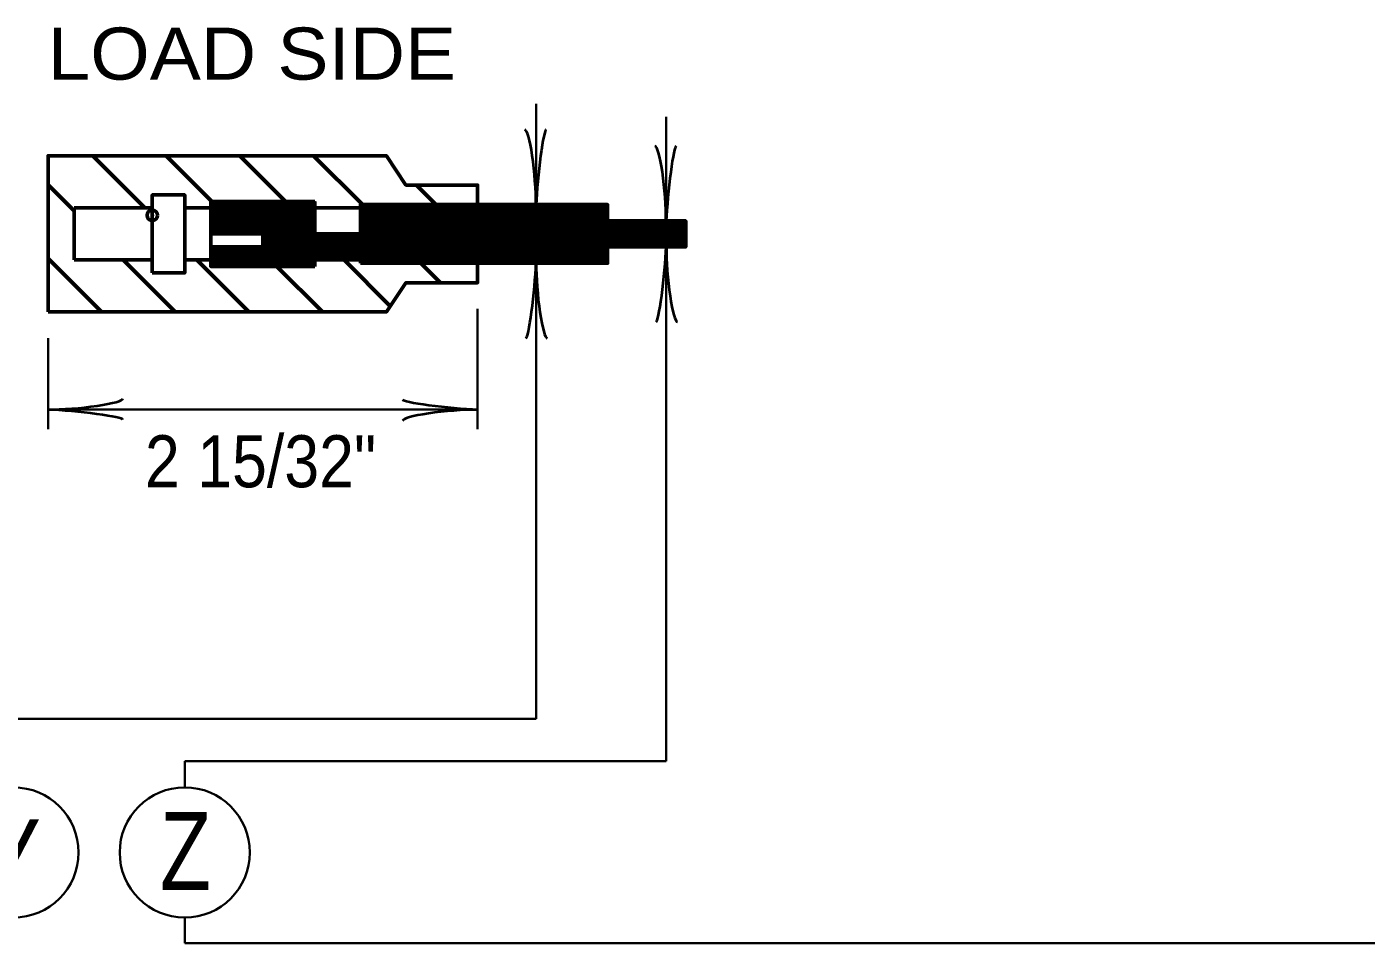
# Model space of a CAD drawing. Extents: x -1 to 679, y 0 to 440.
# Drawn here: x 531 to 582.5, y 359.2 to 394.4 of the extents above; entities that cross this region are included whole.
import ezdxf

# ---------------------------------------------------------------- set-up
doc = ezdxf.new("R2010")
doc.units = 0
doc.header["$LTSCALE"] = 0.8
doc.header["$PDMODE"] = 32
doc.header["$PDSIZE"] = 0.4
doc.layers.add('1', color=7, linetype='Continuous', lineweight=53)

msp = doc.modelspace()

# ---------------------------------------------------------------- linework, layer by layer
at = {"layer": '1', "lineweight": 35}
for p, q in [((550.6135, 387.6022), (550.6135, 391.4772)), ((555.6135, 386.9772), (555.6135, 390.9772)), ((555.6135, 385.9772), (555.6135, 366.2272)), ((550.6135, 385.3522), (550.6135, 367.8522)), ((548.3635, 383.6022), (548.3635, 378.9772)), ((531.8635, 382.4772), (531.8635, 378.9772)), ((531.8635, 379.7272), (548.3635, 379.7272)), ((550.6135, 367.8522), (530.5331, 367.8522)), ((555.6135, 366.2272), (537.1135, 366.2272)), ((537.1135, 366.2272), (537.1135, 365.2133)), ((537.1135, 360.2133), (537.1135, 359.2272)), ((537.1135, 359.2272), (624.4022, 359.2272))]:
    msp.add_line(p, q, dxfattribs=at)
at = {"layer": '1'}
for p, q in [((535.5778, 387.4772), (533.5777, 389.4772)), ((538.1561, 387.7272), (536.4061, 389.4772)), ((540.9847, 387.7272), (539.2346, 389.4772)), ((543.9382, 387.6022), (542.063, 389.4772)), ((532.8635, 387.3629), (531.8635, 388.3629)), ((546.7664, 387.6022), (546.0164, 388.3522)), ((538.1135, 386.5976), (538.1135, 387.7272)), ((538.1135, 387.7065), (538.1342, 387.7272)), ((538.1135, 387.565), (538.2757, 387.7272)), ((538.1135, 387.4236), (538.4171, 387.7272)), ((538.1135, 387.2822), (538.5585, 387.7272)), ((538.1135, 387.1407), (538.6999, 387.7272)), ((538.1135, 386.9993), (538.8413, 387.7272)), ((538.1135, 386.8579), (538.9828, 387.7272)), ((538.1135, 386.7165), (539.1242, 387.7272)), ((538.1135, 386.5751), (539.2656, 387.7272)), ((539.3439, 386.4772), (538.1135, 387.7076)), ((539.2025, 386.4772), (538.1135, 387.5662)), ((538.157, 386.4772), (539.407, 387.7272)), ((539.4854, 386.4772), (538.2354, 387.7272)), ((538.2984, 386.4772), (539.5484, 387.7272)), ((539.6268, 386.4772), (538.3768, 387.7272)), ((538.4398, 386.4772), (539.6898, 387.7272)), ((539.7682, 386.4772), (538.5182, 387.7272)), ((538.5812, 386.4772), (539.8312, 387.7272)), ((539.9097, 386.4772), (538.6597, 387.7272)), ((538.7227, 386.4772), (539.9727, 387.7272)), ((540.0511, 386.4772), (538.8011, 387.7272)), ((538.8641, 386.4772), (540.1141, 387.7272)), ((541.4425, 385.2272), (538.9425, 387.7272)), ((539.0055, 386.4772), (540.2555, 387.7272)), ((541.5839, 385.2272), (539.0839, 387.7272)), ((539.1469, 386.4772), (540.3969, 387.7272)), ((541.7253, 385.2272), (539.2253, 387.7272)), ((539.2883, 386.4772), (540.5383, 387.7272)), ((541.8668, 385.2272), (539.3668, 387.7272)), ((539.4298, 386.4772), (540.6798, 387.7272)), ((539.4526, 385.2272), (541.9526, 387.7272)), ((542.0082, 385.2272), (539.5082, 387.7272)), ((539.5712, 386.4772), (540.8212, 387.7272)), ((539.594, 385.2272), (542.094, 387.7272)), ((542.1135, 385.2632), (539.6496, 387.7272)), ((539.7127, 386.4772), (540.9627, 387.7272)), ((539.7354, 385.2272), (542.1135, 387.6053)), ((542.1135, 385.4047), (539.791, 387.7272)), ((539.8541, 386.4772), (541.1041, 387.7272)), ((542.1135, 385.5461), (539.9324, 387.7272)), ((539.9955, 386.4772), (541.2455, 387.7272)), ((542.1135, 385.6875), (540.0738, 387.7272)), ((540.1135, 386.4538), (541.3869, 387.7272)), ((540.1135, 386.3123), (541.5283, 387.7272)), ((540.1135, 386.1709), (541.6698, 387.7272)), ((540.1135, 386.0295), (541.8112, 387.7272)), ((542.1135, 385.8289), (540.2152, 387.7272)), ((542.1135, 385.9703), (540.3567, 387.7272)), ((542.1135, 386.1117), (540.4981, 387.7272)), ((542.1135, 386.2532), (540.6395, 387.7272)), ((542.1135, 386.3947), (540.781, 387.7272)), ((542.1135, 386.5361), (540.9224, 387.7272)), ((542.1135, 386.6775), (541.0638, 387.7272)), ((542.1135, 386.8189), (541.2052, 387.7272)), ((542.1135, 386.9603), (541.3467, 387.7272)), ((542.1135, 387.1017), (541.4881, 387.7272)), ((542.1135, 387.2432), (541.6295, 387.7272)), ((542.1135, 387.3846), (541.7709, 387.7272)), ((542.1135, 387.526), (541.9123, 387.7272)), ((542.1135, 387.6674), (542.0538, 387.7272)), ((542.1135, 387.7272), (542.1135, 386.4772)), ((543.8635, 387.5183), (543.9473, 387.6022)), ((543.8635, 387.3769), (544.0888, 387.6022)), ((543.8635, 387.2354), (544.2302, 387.6022)), ((543.8635, 387.094), (544.3717, 387.6022)), ((543.8635, 386.9526), (544.5131, 387.6022)), ((543.8635, 386.8112), (544.6545, 387.6022)), ((543.8635, 386.6697), (544.7959, 387.6022)), ((543.8635, 386.5283), (544.9373, 387.6022)), ((543.8635, 386.3869), (545.0788, 387.6022)), ((543.8635, 386.2455), (545.2202, 387.6022)), ((543.8635, 386.1041), (545.3616, 387.6022)), ((543.8635, 385.9627), (545.503, 387.6022)), ((543.8635, 385.8212), (545.6444, 387.6022)), ((543.8635, 385.6798), (545.7858, 387.6022)), ((543.8635, 385.5384), (545.9272, 387.6022)), ((543.8635, 385.397), (546.0687, 387.6022)), ((546.1218, 385.3522), (543.8718, 387.6022)), ((543.9601, 385.3522), (546.2101, 387.6022)), ((546.2632, 385.3522), (544.0132, 387.6022)), ((544.1015, 385.3522), (546.3515, 387.6022)), ((546.4047, 385.3522), (544.1547, 387.6022)), ((544.2429, 385.3522), (546.4929, 387.6022)), ((546.5461, 385.3522), (544.2961, 387.6022)), ((544.3843, 385.3522), (546.6343, 387.6022)), ((546.6875, 385.3522), (544.4375, 387.6022)), ((544.5258, 385.3522), (546.7758, 387.6022)), ((546.8289, 385.3522), (544.5789, 387.6022)), ((544.6672, 385.3522), (546.9172, 387.6022)), ((546.9703, 385.3522), (544.7203, 387.6022)), ((544.8087, 385.3522), (547.0587, 387.6022)), ((547.1118, 385.3522), (544.8618, 387.6022)), ((544.9501, 385.3522), (547.2001, 387.6022)), ((547.2532, 385.3522), (545.0032, 387.6022)), ((545.0915, 385.3522), (547.3415, 387.6022)), ((547.3947, 385.3522), (545.1447, 387.6022)), ((545.2329, 385.3522), (547.4829, 387.6022)), ((547.5361, 385.3522), (545.2861, 387.6022)), ((545.3743, 385.3522), (547.6243, 387.6022)), ((547.6775, 385.3522), (545.4275, 387.6022)), ((545.5158, 385.3522), (547.7658, 387.6022)), ((547.8189, 385.3522), (545.5689, 387.6022)), ((545.6572, 385.3522), (547.9072, 387.6022)), ((547.9603, 385.3522), (545.7103, 387.6022)), ((545.7986, 385.3522), (548.0486, 387.6022)), ((548.1018, 385.3522), (545.8518, 387.6022)), ((545.94, 385.3522), (548.19, 387.6022)), ((548.2432, 385.3522), (545.9932, 387.6022)), ((546.0814, 385.3522), (548.3314, 387.6022)), ((548.3846, 385.3522), (546.1346, 387.6022)), ((546.2228, 385.3522), (548.4728, 387.6022)), ((548.526, 385.3522), (546.276, 387.6022)), ((546.3642, 385.3522), (548.6142, 387.6022)), ((548.6674, 385.3522), (546.4174, 387.6022)), ((546.5057, 385.3522), (548.7557, 387.6022)), ((548.8088, 385.3522), (546.5588, 387.6022)), ((546.6471, 385.3522), (548.8971, 387.6022)), ((548.9502, 385.3522), (546.7002, 387.6022)), ((546.7885, 385.3522), (549.0385, 387.6022)), ((549.0917, 385.3522), (546.8417, 387.6022)), ((546.93, 385.3522), (549.18, 387.6022)), ((549.2331, 385.3522), (546.9831, 387.6022)), ((547.0714, 385.3522), (549.3214, 387.6022)), ((549.3745, 385.3522), (547.1245, 387.6022)), ((547.2128, 385.3522), (549.4628, 387.6022)), ((549.5159, 385.3522), (547.2659, 387.6022)), ((547.3542, 385.3522), (549.6042, 387.6022)), ((549.6573, 385.3522), (547.4073, 387.6022)), ((547.4957, 385.3522), (549.7457, 387.6022)), ((549.7987, 385.3522), (547.5487, 387.6022)), ((547.6371, 385.3522), (549.8871, 387.6022)), ((549.9402, 385.3522), (547.6902, 387.6022)), ((547.7785, 385.3522), (550.0285, 387.6022)), ((550.0817, 385.3522), (547.8317, 387.6022)), ((547.9199, 385.3522), (550.1699, 387.6022)), ((550.2231, 385.3522), (547.9731, 387.6022)), ((548.0613, 385.3522), (550.3113, 387.6022)), ((550.3645, 385.3522), (548.1145, 387.6022)), ((548.2028, 385.3522), (550.4528, 387.6022)), ((550.5059, 385.3522), (548.2559, 387.6022)), ((548.3442, 385.3522), (550.5942, 387.6022)), ((550.6473, 385.3522), (548.3973, 387.6022)), ((548.4856, 385.3522), (550.7356, 387.6022)), ((550.7887, 385.3522), (548.5387, 387.6022)), ((548.627, 385.3522), (550.877, 387.6022)), ((550.9302, 385.3522), (548.6802, 387.6022)), ((548.7684, 385.3522), (551.0184, 387.6022)), ((551.0716, 385.3522), (548.8216, 387.6022)), ((548.9098, 385.3522), (551.1598, 387.6022)), ((551.213, 385.3522), (548.963, 387.6022)), ((549.0512, 385.3522), (551.3012, 387.6022)), ((551.3544, 385.3522), (549.1044, 387.6022)), ((549.1927, 385.3522), (551.4427, 387.6022)), ((551.4958, 385.3522), (549.2458, 387.6022)), ((549.3341, 385.3522), (551.5841, 387.6022)), ((551.6372, 385.3522), (549.3872, 387.6022)), ((549.4756, 385.3522), (551.7256, 387.6022)), ((551.7787, 385.3522), (549.5287, 387.6022)), ((549.617, 385.3522), (551.867, 387.6022)), ((551.9201, 385.3522), (549.6701, 387.6022)), ((549.7584, 385.3522), (552.0084, 387.6022)), ((552.0615, 385.3522), (549.8115, 387.6022)), ((549.8998, 385.3522), (552.1498, 387.6022)), ((552.2029, 385.3522), (549.9529, 387.6022)), ((550.0412, 385.3522), (552.2912, 387.6022)), ((552.3443, 385.3522), (550.0943, 387.6022)), ((550.1827, 385.3522), (552.4327, 387.6022)), ((552.4858, 385.3522), (550.2358, 387.6022)), ((550.3241, 385.3522), (552.5741, 387.6022)), ((552.6273, 385.3522), (550.3773, 387.6022)), ((550.4655, 385.3522), (552.7155, 387.6022)), ((552.7687, 385.3522), (550.5187, 387.6022)), ((550.6069, 385.3522), (552.8569, 387.6022)), ((552.9101, 385.3522), (550.6601, 387.6022)), ((550.7483, 385.3522), (552.9983, 387.6022)), ((553.0515, 385.3522), (550.8015, 387.6022)), ((550.8897, 385.3522), (553.1397, 387.6022)), ((553.1929, 385.3522), (550.9429, 387.6022)), ((551.0312, 385.3522), (553.2812, 387.6022)), ((553.3343, 385.3522), (551.0843, 387.6022)), ((553.3635, 385.4644), (551.2257, 387.6022)), ((553.3635, 385.6058), (551.3672, 387.6022)), ((553.3635, 385.7473), (551.5086, 387.6022)), ((553.3635, 385.8887), (551.65, 387.6022)), ((553.4164, 385.9772), (551.7914, 387.6022)), ((553.5578, 385.9772), (551.9328, 387.6022)), ((553.6993, 385.9772), (552.0743, 387.6022)), ((553.8407, 385.9772), (552.2157, 387.6022)), ((553.9821, 385.9772), (552.3571, 387.6022)), ((554.1235, 385.9772), (552.4985, 387.6022)), ((554.2649, 385.9772), (552.6399, 387.6022)), ((553.3635, 387.0201), (552.7814, 387.6022)), ((553.3635, 387.1615), (552.9228, 387.6022)), ((553.3635, 387.3029), (553.0643, 387.6022)), ((553.3635, 387.4443), (553.2057, 387.6022)), ((553.3635, 387.5857), (553.3471, 387.6022)), ((532.8635, 387.4772), (532.8635, 385.4772)), ((532.8635, 387.4772), (535.8635, 387.4772)), ((537.1135, 387.4772), (538.1135, 387.4772)), ((539.0611, 386.4772), (538.1135, 387.4247)), ((538.9197, 386.4772), (538.1135, 387.2833)), ((538.7782, 386.4772), (538.1135, 387.1419)), ((539.8768, 385.2272), (542.1135, 387.4638)), ((540.0182, 385.2272), (542.1135, 387.3224)), ((540.1597, 385.2272), (542.1135, 387.181)), ((540.3011, 385.2272), (542.1135, 387.0396)), ((542.1135, 387.4772), (543.8635, 387.4772)), ((545.9804, 385.3522), (543.8635, 387.4691)), ((545.839, 385.3522), (543.8635, 387.3277)), ((545.6976, 385.3522), (543.8635, 387.1862)), ((545.5562, 385.3522), (543.8635, 387.0448)), ((551.1726, 385.3522), (553.3635, 387.5431)), ((551.314, 385.3522), (553.3635, 387.4017)), ((551.4554, 385.3522), (553.3635, 387.2602)), ((551.5968, 385.3522), (553.3635, 387.1188)), ((538.6368, 386.4772), (538.1135, 387.0005)), ((538.4954, 386.4772), (538.1135, 386.8591)), ((538.354, 386.4772), (538.1135, 386.7177)), ((538.2126, 386.4772), (538.1135, 386.5762)), ((540.4425, 385.2272), (542.1135, 386.8982)), ((540.5839, 385.2272), (542.1135, 386.7568)), ((540.7254, 385.2272), (542.1135, 386.6153)), ((545.4148, 385.3522), (543.8635, 386.9034)), ((545.2733, 385.3522), (543.8635, 386.762)), ((545.1319, 385.3522), (543.8635, 386.6206)), ((551.7382, 385.3522), (553.3635, 386.9774)), ((551.8797, 385.3522), (553.5047, 386.9772)), ((552.0212, 385.3522), (553.6462, 386.9772)), ((552.1626, 385.3522), (553.7876, 386.9772)), ((552.304, 385.3522), (553.929, 386.9772)), ((552.4454, 385.3522), (554.0704, 386.9772)), ((552.5868, 385.3522), (554.2118, 386.9772)), ((552.7283, 385.3522), (554.3533, 386.9772)), ((554.4064, 385.9772), (553.4064, 386.9772)), ((553.4947, 385.9772), (554.4947, 386.9772)), ((554.5478, 385.9772), (553.5478, 386.9772)), ((553.6361, 385.9772), (554.6361, 386.9772)), ((554.6893, 385.9772), (553.6893, 386.9772)), ((553.7775, 385.9772), (554.7775, 386.9772)), ((554.8307, 385.9772), (553.8307, 386.9772)), ((553.9189, 385.9772), (554.9189, 386.9772)), ((554.9721, 385.9772), (553.9721, 386.9772)), ((554.0603, 385.9772), (555.0603, 386.9772)), ((555.1135, 385.9772), (554.1135, 386.9772)), ((554.2017, 385.9772), (555.2017, 386.9772)), ((555.2549, 385.9772), (554.2549, 386.9772)), ((554.3432, 385.9772), (555.3432, 386.9772)), ((555.3963, 385.9772), (554.3963, 386.9772)), ((554.4846, 385.9772), (555.4846, 386.9772)), ((555.5377, 385.9772), (554.5377, 386.9772)), ((554.626, 385.9772), (555.626, 386.9772)), ((555.6792, 385.9772), (554.6792, 386.9772)), ((554.7674, 385.9772), (555.7674, 386.9772)), ((555.8206, 385.9772), (554.8206, 386.9772)), ((554.9088, 385.9772), (555.9088, 386.9772)), ((555.962, 385.9772), (554.962, 386.9772)), ((555.0503, 385.9772), (556.0503, 386.9772)), ((556.1034, 385.9772), (555.1034, 386.9772)), ((555.1917, 385.9772), (556.1917, 386.9772)), ((556.2448, 385.9772), (555.2448, 386.9772)), ((555.3332, 385.9772), (556.3332, 386.9772)), ((556.3635, 385.9999), (555.3863, 386.9772)), ((555.4746, 385.9772), (556.3635, 386.8661)), ((556.3635, 386.1413), (555.5277, 386.9772)), ((555.616, 385.9772), (556.3635, 386.7247)), ((556.3635, 386.2827), (555.6691, 386.9772)), ((555.7574, 385.9772), (556.3635, 386.5832)), ((556.3635, 386.4242), (555.8106, 386.9772)), ((556.3635, 386.5657), (555.952, 386.9772)), ((556.3635, 386.7071), (556.0934, 386.9772)), ((556.3635, 386.8485), (556.2348, 386.9772)), ((538.1135, 385.9772), (538.1135, 386.4772)), ((541.3011, 385.2272), (540.1135, 386.4147)), ((541.1597, 385.2272), (540.1135, 386.2733)), ((541.0182, 385.2272), (540.1135, 386.1319)), ((540.8668, 385.2272), (542.1135, 386.4738)), ((541.0082, 385.2272), (542.1135, 386.3324)), ((541.1497, 385.2272), (542.1135, 386.191)), ((541.2911, 385.2272), (542.1135, 386.0496)), ((542.1135, 386.4613), (542.1294, 386.4772)), ((542.1135, 386.3198), (542.2708, 386.4772)), ((542.1135, 386.1784), (542.4122, 386.4772)), ((542.1135, 386.037), (542.5537, 386.4772)), ((542.1135, 385.8956), (542.6951, 386.4772)), ((542.1135, 385.7542), (542.8365, 386.4772)), ((542.1135, 385.6127), (542.978, 386.4772)), ((542.9733, 385.4772), (542.1135, 386.3369)), ((542.8318, 385.4772), (542.1135, 386.1955)), ((542.6904, 385.4772), (542.1135, 386.0541)), ((543.1147, 385.4772), (542.1147, 386.4772)), ((542.1194, 385.4772), (543.1194, 386.4772)), ((543.2561, 385.4772), (542.2561, 386.4772)), ((542.2608, 385.4772), (543.2608, 386.4772)), ((543.3975, 385.4772), (542.3975, 386.4772)), ((542.4022, 385.4772), (543.4022, 386.4772)), ((543.5389, 385.4772), (542.5389, 386.4772)), ((542.5437, 385.4772), (543.5437, 386.4772)), ((543.6803, 385.4772), (542.6803, 386.4772)), ((542.6851, 385.4772), (543.6851, 386.4772)), ((543.8217, 385.4772), (542.8217, 386.4772)), ((542.8265, 385.4772), (543.8265, 386.4772)), ((543.8635, 385.5768), (542.9632, 386.4772)), ((542.9679, 385.4772), (543.8635, 386.3727)), ((543.8635, 385.7183), (543.1046, 386.4772)), ((543.1093, 385.4772), (543.8635, 386.2313)), ((543.8635, 385.8597), (543.246, 386.4772)), ((543.2507, 385.4772), (543.8635, 386.0899)), ((543.8635, 386.0012), (543.3875, 386.4772)), ((543.8635, 386.1426), (543.5289, 386.4772)), ((543.8635, 386.284), (543.6703, 386.4772)), ((543.8635, 386.4254), (543.8117, 386.4772)), ((544.9905, 385.3522), (543.8635, 386.4792)), ((543.8635, 385.3522), (543.8635, 386.4772)), ((544.849, 385.3522), (543.8635, 386.3377)), ((544.7076, 385.3522), (543.8635, 386.1962)), ((544.5662, 385.3522), (543.8635, 386.0548)), ((555.8988, 385.9772), (556.3635, 386.4418)), ((556.0403, 385.9772), (556.3635, 386.3004)), ((556.1817, 385.9772), (556.3635, 386.159)), ((556.3231, 385.9772), (556.3635, 386.0176)), ((533.9208, 383.4772), (531.8635, 385.5345)), ((538.1135, 385.868), (538.2227, 385.9772)), ((538.1135, 385.7266), (538.3641, 385.9772)), ((538.1135, 385.5852), (538.5055, 385.9772)), ((538.1135, 385.4437), (538.6469, 385.9772)), ((538.1135, 385.3023), (538.7883, 385.9772)), ((538.7555, 385.2272), (538.1135, 385.8692)), ((538.6141, 385.2272), (538.1135, 385.7278)), ((538.4727, 385.2272), (538.1135, 385.5863)), ((538.8969, 385.2272), (538.1469, 385.9772)), ((538.1798, 385.2272), (538.9298, 385.9772)), ((539.0383, 385.2272), (538.2883, 385.9772)), ((538.3212, 385.2272), (539.0712, 385.9772)), ((539.1798, 385.2272), (538.4298, 385.9772)), ((538.4627, 385.2272), (539.2127, 385.9772)), ((539.3212, 385.2272), (538.5712, 385.9772)), ((538.6041, 385.2272), (539.3541, 385.9772)), ((539.4626, 385.2272), (538.7126, 385.9772)), ((538.7455, 385.2272), (539.4955, 385.9772)), ((539.604, 385.2272), (538.854, 385.9772)), ((538.8869, 385.2272), (539.6369, 385.9772)), ((539.7454, 385.2272), (538.9954, 385.9772)), ((539.0283, 385.2272), (539.7783, 385.9772)), ((539.8868, 385.2272), (539.1368, 385.9772)), ((539.1698, 385.2272), (539.9198, 385.9772)), ((540.0282, 385.2272), (539.2782, 385.9772)), ((539.3112, 385.2272), (540.0612, 385.9772)), ((540.1697, 385.2272), (539.4197, 385.9772)), ((540.3111, 385.2272), (539.5611, 385.9772)), ((540.4525, 385.2272), (539.7025, 385.9772)), ((540.5939, 385.2272), (539.8439, 385.9772)), ((540.7354, 385.2272), (539.9854, 385.9772)), ((540.8768, 385.2272), (540.1135, 385.9905)), ((541.4325, 385.2272), (542.1135, 385.9082)), ((541.5739, 385.2272), (542.1135, 385.7668)), ((541.7153, 385.2272), (542.1135, 385.6253)), ((542.549, 385.4772), (542.1135, 385.9127)), ((542.4076, 385.4772), (542.1135, 385.7713)), ((542.2662, 385.4772), (542.1135, 385.6298)), ((543.3922, 385.4772), (543.8635, 385.9485)), ((543.5336, 385.4772), (543.8635, 385.8071)), ((543.675, 385.4772), (543.8635, 385.6657)), ((543.8164, 385.4772), (543.8635, 385.5242)), ((544.4248, 385.3522), (543.8635, 385.9134)), ((544.2833, 385.3522), (543.8635, 385.772)), ((544.1419, 385.3522), (543.8635, 385.6306)), ((552.8697, 385.3522), (553.3635, 385.846)), ((553.0111, 385.3522), (553.3635, 385.7046)), ((553.1525, 385.3522), (553.3635, 385.5632)), ((532.8635, 385.4772), (535.8635, 385.4772)), ((536.7492, 383.4772), (534.7492, 385.4772)), ((537.1135, 385.4772), (538.1135, 385.4772)), ((539.5777, 383.4772), (537.5777, 385.4772)), ((538.3312, 385.2272), (538.1135, 385.4449)), ((538.1898, 385.2272), (538.1135, 385.3034)), ((542.4061, 383.4772), (540.6562, 385.2272)), ((541.8568, 385.2272), (542.1135, 385.4839)), ((541.9982, 385.2272), (542.1135, 385.3425)), ((542.1247, 385.4772), (542.1135, 385.4884)), ((542.1135, 385.4772), (542.1135, 385.2272)), ((545.0119, 383.6998), (543.2346, 385.4772)), ((544.0005, 385.3522), (543.8635, 385.4892)), ((546.938, 384.6022), (546.188, 385.3522)), ((553.2939, 385.3522), (553.3635, 385.4217))]:
    msp.add_line(p, q, dxfattribs=at)
for points in [[(531.8635, 383.4772), (531.8635, 389.4772), (544.8635, 389.4772), (545.6135, 388.3522), (548.3635, 388.3522), (548.3635, 387.6022)], [(538.1135, 385.9772), (538.1135, 386.4772), (538.1135, 387.7272), (542.1135, 387.7272)], [(542.1135, 385.2272), (538.1135, 385.2272), (538.1135, 385.9772), (540.1135, 385.9772), (540.1135, 386.4772), (538.1135, 386.4772)], [(548.3635, 385.3522), (548.3635, 384.6022), (545.6135, 384.6022), (544.8635, 383.4772), (531.8635, 383.4772)]]:
    msp.add_lwpolyline(points, dxfattribs=at)
for points in [[(535.8635, 384.9772), (535.8635, 387.9772), (537.1135, 387.9772), (537.1135, 384.9772)], [(535.8635, 384.9772), (535.8635, 387.9772), (537.1135, 387.9772), (537.1135, 384.9772)], [(543.8635, 385.3522), (543.8635, 385.4772), (543.8635, 386.4772), (543.8635, 387.6022), (553.3635, 387.6022), (553.3635, 386.9772), (556.3635, 386.9772), (556.3635, 385.9772), (553.3635, 385.9772), (553.3635, 385.3522)], [(542.1135, 385.4772), (542.1135, 386.4772), (543.8635, 386.4772), (543.8635, 385.4772)]]:
    msp.add_lwpolyline(points, close=True, dxfattribs=at)
at = {"layer": '1', "lineweight": 35}
for centre in [(530.5331, 362.7133), (537.1135, 362.7133)]:
    msp.add_circle(centre, 2.5, dxfattribs=at)
at = {"layer": '1', "lineweight": 40}
for centre, major_axis, ratio, start_param, end_param in [((550.3372, 388.6934), (0.1562, -1.7857), 0.122415, 0.8963533, 3.1415927), ((550.3372, 388.6934), (0.1562, -1.7857), 0.122415, 0.8963533, 3.1415927), ((550.8251, 388.7227), (-0.1757, -1.7565), 0.07063, 3.1407148, 5.41811), ((550.8251, 388.7227), (-0.1757, -1.7565), 0.07063, 3.1407148, 5.41811), ((555.3372, 388.0684), (0.1562, -1.7857), 0.122415, 0.8963533, 3.1415927), ((555.8251, 388.0977), (-0.1757, -1.7565), 0.07063, 3.1407148, 5.41811), ((555.4019, 384.8567), (0.1757, 1.7565), 0.07063, 3.1407148, 5.41811), ((555.8898, 384.886), (-0.1562, 1.7857), 0.122415, 0.8963533, 3.1415927), ((550.4019, 384.2317), (0.1757, 1.7565), 0.07063, 3.1407148, 5.41811), ((550.4019, 384.2317), (0.1757, 1.7565), 0.07063, 3.1407148, 5.41811), ((550.8898, 384.261), (-0.1562, 1.7857), 0.122415, 0.8963533, 3.1415927), ((550.8898, 384.261), (-0.1562, 1.7857), 0.122415, 0.8963533, 3.1415927), ((532.9547, 380.0035), (-1.7857, -0.1562), 0.122415, 0.8963533, 3.1415927), ((532.9547, 380.0035), (-1.7857, -0.1562), 0.122415, 0.8963533, 3.1415927), ((547.243, 379.9388), (1.7565, -0.1757), 0.07063, 3.1407148, 5.41811), ((532.984, 379.5156), (-1.7565, 0.1757), 0.07063, 3.1407148, 5.41811), ((532.984, 379.5156), (-1.7565, 0.1757), 0.07063, 3.1407148, 5.41811), ((547.2723, 379.4509), (1.7857, 0.1562), 0.122415, 0.8963533, 3.1415927)]:
    msp.add_ellipse(centre, major_axis=major_axis, ratio=ratio, start_param=start_param, end_param=end_param, dxfattribs=at)
at = {"layer": '1'}
msp.add_point((535.8635, 387.1913), dxfattribs=at)

# ---------------------------------------------------------------- texts
for s, height, width, p in [('LOAD SIDE', 2, 1.1, (531.8462, 392.4045)), ('2 15/32"', 2, 0.9, (535.5851, 376.7426)), ('Y', 3, 0.85, (529.3167, 360.9921)), ('Z', 3, 0.8, (536.1634, 361.266))]:
    msp.add_text(s, height=height, dxfattribs=dict(at, width=width)).set_placement(p)

doc.saveas('drawing.dxf')
